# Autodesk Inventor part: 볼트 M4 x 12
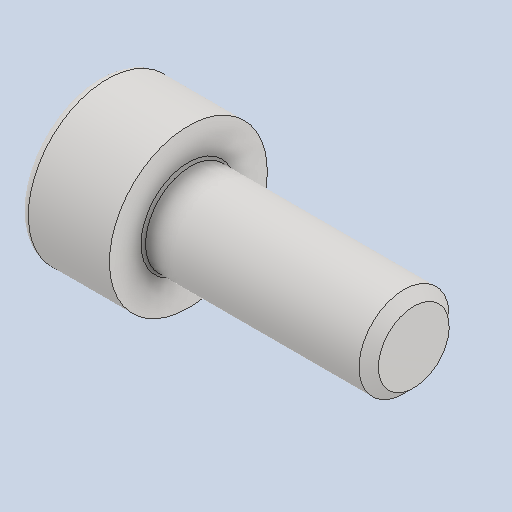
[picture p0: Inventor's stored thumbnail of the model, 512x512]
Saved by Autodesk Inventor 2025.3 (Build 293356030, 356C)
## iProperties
Created: 2025-08
Part Number: 볼트 M4 x 12
Material: 스테인리스강
Description: 6각머리 태핑 나사
Document SubType Name: Modeling
Designer: infra011
Density: 8.08 g/cm^3
Appearance: 기본값
Author: jhkim
Sending System: Autodesk Inventor 2026
Preprocessor: ST-DEVELOPER v20.1
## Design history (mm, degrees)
feature "Solid1"
node "솔리드1"
